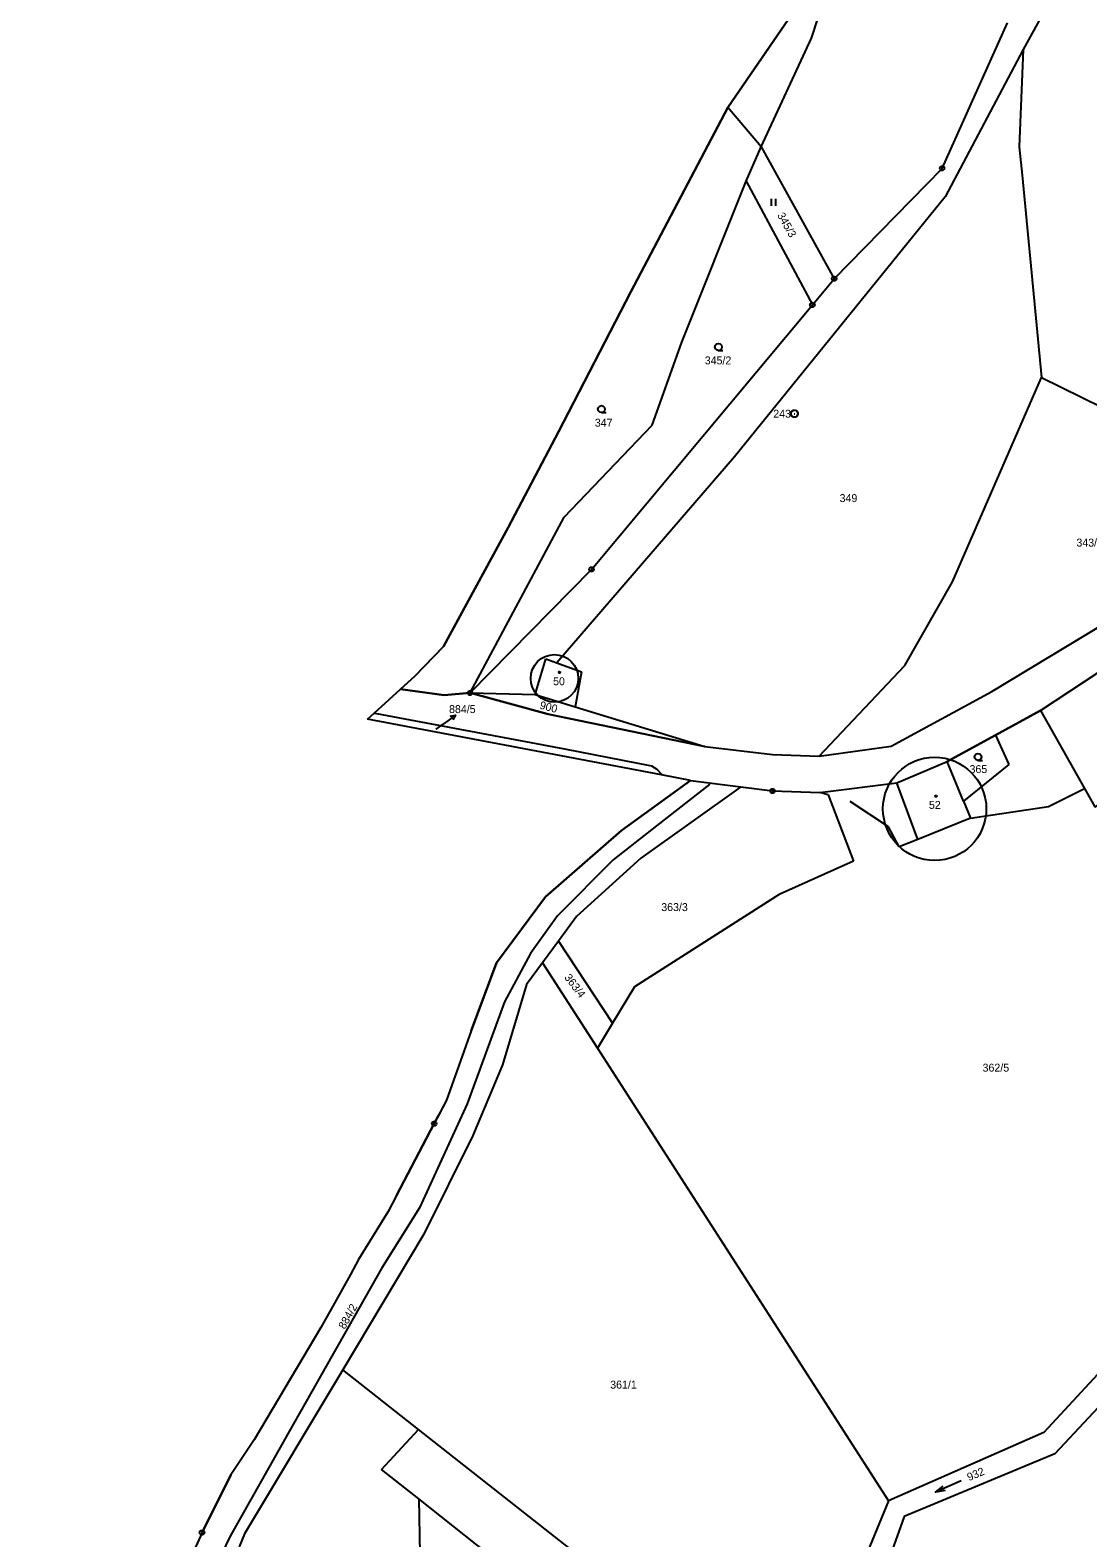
# Model space of a CAD drawing. Extents: x -580551 to -575069, y -1073031 to -1067931.
# Drawn here: x -577570.7 to -577343.9, y -1070091.5 to -1069768.1 of the extents above; entities that cross this region are included whole.
import ezdxf

# ---------------------------------------------------------------- set-up
doc = ezdxf.new("R2010")
doc.units = 0
for name, color, linetype in [('Druh pozemku', 7, 'Continuous'), ('Geodetické body', 7, 'Continuous'), ('Katastrální hranice', 7, 'Continuous'), ('Parcela', 7, 'Continuous'), ('Parcelní číslo', 7, 'Continuous'), ('Parcelní číslo_stavba', 7, 'Continuous'), ('Pomocná vrstva', 7, 'Continuous'), ('SR - hranice státu', 7, 'Continuous'), ('stavební parcely', 7, 'Continuous'), ('Vnitřní kresba', 7, 'Continuous'), ('Vrstva 6', 7, 'Continuous'), ('ČR - rámy ML', 7, 'Continuous')]:
    doc.layers.add(name, color=color, linetype=linetype)

msp = doc.modelspace()

# ---------------------------------------------------------------- linework, layer by layer
at = {"layer": 'Druh pozemku'}
for p, q in [((-577411.75, -1069804.33), (-577411.75, -1069805.83)), ((-577410.75, -1069805.83), (-577410.75, -1069804.33)), ((-577371.014, -1070079.312), (-577376.506, -1070081.728))]:
    msp.add_line(p, q, dxfattribs=at)
for points in [[(-577423.08, -1069836.83), (-577423.46, -1069836.73), (-577423.73, -1069836.46), (-577423.83, -1069836.09), (-577423.73, -1069835.72), (-577423.46, -1069835.45), (-577423.09, -1069835.35), (-577422.72, -1069835.45), (-577422.45, -1069835.72), (-577422.35, -1069836.1), (-577422.45, -1069836.48), (-577422.72, -1069836.75), (-577423.1, -1069836.85), (-577422.1, -1069836.85)], [(-577448.16, -1069850.15), (-577448.54, -1069850.05), (-577448.81, -1069849.78), (-577448.91, -1069849.41), (-577448.81, -1069849.04), (-577448.54, -1069848.77), (-577448.17, -1069848.67), (-577447.8, -1069848.77), (-577447.53, -1069849.04), (-577447.43, -1069849.42), (-577447.53, -1069849.8), (-577447.8, -1069850.07), (-577448.18, -1069850.17), (-577447.18, -1069850.17)], [(-577367.41, -1069924.76), (-577367.79, -1069924.66), (-577368.06, -1069924.39), (-577368.16, -1069924.02), (-577368.06, -1069923.65), (-577367.79, -1069923.38), (-577367.42, -1069923.28), (-577367.05, -1069923.38), (-577366.78, -1069923.65), (-577366.68, -1069924.03), (-577366.78, -1069924.41), (-577367.05, -1069924.68), (-577367.43, -1069924.78), (-577366.43, -1069924.78)], [(-577374.474, -1070081.38), (-577376.506, -1070081.728), (-577374.877, -1070080.465)]]:
    msp.add_lwpolyline(points, dxfattribs=at)
for points in [[(-577457.06, -1069905.73), (-577456.97, -1069905.88), (-577457.06, -1069906.03), (-577457.24, -1069906.03), (-577457.33, -1069905.88), (-577457.24, -1069905.73)], [(-577376.34, -1069932.27), (-577376.25, -1069932.42), (-577376.34, -1069932.57), (-577376.52, -1069932.57), (-577376.61, -1069932.42), (-577376.52, -1069932.27)]]:
    msp.add_lwpolyline(points, close=True, dxfattribs=at)
at = {"layer": 'Geodetické body'}
for p, q in [((-577375.24, -1069797.78), (-577375, -1069797.78)), ((-577398.38, -1069821.45), (-577398.14, -1069821.45)), ((-577403.06, -1069827.06), (-577402.82, -1069827.06)), ((-577406.82, -1069850.4), (-577406.72, -1069850.4)), ((-577450.41, -1069883.81), (-577450.17, -1069883.81)), ((-577476.45, -1069910.3), (-577476.21, -1069910.3)), ((-577411.59, -1069931.33), (-577411.35, -1069931.33)), ((-577484.14, -1070002.69), (-577483.9, -1070002.69)), ((-577533.93, -1070090.41), (-577533.69, -1070090.41))]:
    msp.add_line(p, q, dxfattribs=at)
for points in [[(-577374.97, -1069797.3), (-577374.72, -1069797.48), (-577374.62, -1069797.77), (-577374.72, -1069798.06), (-577374.97, -1069798.24), (-577375.28, -1069798.24), (-577375.53, -1069798.06), (-577375.63, -1069797.77), (-577375.53, -1069797.48), (-577375.28, -1069797.3)], [(-577398.11, -1069820.97), (-577397.86, -1069821.15), (-577397.76, -1069821.44), (-577397.86, -1069821.73), (-577398.11, -1069821.91), (-577398.42, -1069821.91), (-577398.67, -1069821.73), (-577398.77, -1069821.44), (-577398.67, -1069821.15), (-577398.42, -1069820.97)], [(-577402.79, -1069826.58), (-577402.54, -1069826.76), (-577402.44, -1069827.05), (-577402.54, -1069827.34), (-577402.79, -1069827.52), (-577403.1, -1069827.52), (-577403.35, -1069827.34), (-577403.45, -1069827.05), (-577403.35, -1069826.76), (-577403.1, -1069826.58)], [(-577406.58, -1069849.68), (-577406.24, -1069849.87), (-577406.05, -1069850.21), (-577406.05, -1069850.6), (-577406.24, -1069850.94), (-577406.58, -1069851.13), (-577406.97, -1069851.13), (-577407.31, -1069850.94), (-577407.5, -1069850.6), (-577407.5, -1069850.21), (-577407.31, -1069849.87), (-577406.97, -1069849.68)], [(-577450.14, -1069883.33), (-577449.89, -1069883.51), (-577449.79, -1069883.8), (-577449.89, -1069884.09), (-577450.14, -1069884.27), (-577450.45, -1069884.27), (-577450.7, -1069884.09), (-577450.8, -1069883.8), (-577450.7, -1069883.51), (-577450.45, -1069883.33)], [(-577476.18, -1069909.82), (-577475.93, -1069910), (-577475.83, -1069910.29), (-577475.93, -1069910.58), (-577476.18, -1069910.76), (-577476.49, -1069910.76), (-577476.74, -1069910.58), (-577476.84, -1069910.29), (-577476.74, -1069910), (-577476.49, -1069909.82)], [(-577411.32, -1069930.85), (-577411.07, -1069931.03), (-577410.97, -1069931.32), (-577411.07, -1069931.61), (-577411.32, -1069931.79), (-577411.63, -1069931.79), (-577411.88, -1069931.61), (-577411.98, -1069931.32), (-577411.88, -1069931.03), (-577411.63, -1069930.85)], [(-577483.87, -1070002.21), (-577483.62, -1070002.39), (-577483.52, -1070002.68), (-577483.62, -1070002.97), (-577483.87, -1070003.15), (-577484.18, -1070003.15), (-577484.43, -1070002.97), (-577484.53, -1070002.68), (-577484.43, -1070002.39), (-577484.18, -1070002.21)], [(-577533.66, -1070089.93), (-577533.41, -1070090.11), (-577533.31, -1070090.4), (-577533.41, -1070090.69), (-577533.66, -1070090.87), (-577533.97, -1070090.87), (-577534.22, -1070090.69), (-577534.32, -1070090.4), (-577534.22, -1070090.11), (-577533.97, -1070089.93)]]:
    msp.add_lwpolyline(points, close=True, dxfattribs=at)
at = {"layer": 'Katastrální hranice'}
for p, q in [((-577421.07, -1069784.74), (-577408.08, -1069765.76)), ((-577441.89, -1069824.3), (-577421.07, -1069784.74)), ((-577457.34, -1069854.3), (-577441.89, -1069824.3)), ((-577468.17, -1069874.85), (-577457.34, -1069854.3)), ((-577482, -1069900.31), (-577468.17, -1069874.85)), ((-577488.19, -1069906.73), (-577482, -1069900.31)), ((-577491.26, -1069909.51), (-577488.19, -1069906.73)), ((-577496.93, -1069914.65), (-577491.26, -1069909.51)), ((-577498.36, -1069915.94), (-577496.93, -1069914.65)), ((-577435.32, -1069927.87), (-577498.36, -1069915.94)), ((-577443.86, -1069939.81), (-577429.05, -1069929.06)), ((-577429.05, -1069929.06), (-577435.32, -1069927.87)), ((-577460.15, -1069954.05), (-577443.86, -1069939.81)), ((-577470.65, -1069968.18), (-577460.15, -1069954.05)), ((-577476.13, -1069982.8), (-577470.65, -1069968.18)), ((-577476.13, -1069982.8), (-577481.37, -1069997.64)), ((-577481.37, -1069997.64), (-577483.09, -1070000.91)), ((-577484.02, -1070002.69), (-577483.09, -1070000.91)), ((-577492.09, -1070018.1), (-577484.02, -1070002.69)), ((-577492.09, -1070018.1), (-577493.9, -1070021.54)), ((-577493.9, -1070021.54), (-577500.24, -1070031.8)), ((-577500.24, -1070031.8), (-577502.01, -1070035.04)), ((-577502.01, -1070035.04), (-577505.38, -1070041.2)), ((-577505.38, -1070041.2), (-577508.36, -1070046.45)), ((-577508.36, -1070046.45), (-577516.05, -1070059.43)), ((-577516.05, -1070059.43), (-577522.62, -1070070.51)), ((-577522.62, -1070070.51), (-577527.65, -1070078.04)), ((-577533.81, -1070090.41), (-577527.65, -1070078.04)), ((-577533.81, -1070090.41), (-577538.93, -1070101.78))]:
    msp.add_line(p, q, dxfattribs=at)
at = {"layer": 'Parcela'}
for p, q in [((-577403.1, -1069769.84), (-577393.88, -1069741.46)), ((-577352.75, -1069763.2), (-577357.71, -1069772.28)), ((-577375.12, -1069797.78), (-577361.12, -1069766.57)), ((-577413.89, -1069793.18), (-577403.1, -1069769.84)), ((-577357.71, -1069772.28), (-577374.49, -1069803.88)), ((-577357.71, -1069772.28), (-577358.61, -1069793.17)), ((-577413.89, -1069793.18), (-577421.07, -1069784.74)), ((-577417.11, -1069800.56), (-577413.89, -1069793.18)), ((-577358.61, -1069793.17), (-577357.92, -1069799.27)), ((-577430.91, -1069835.03), (-577417.11, -1069800.56)), ((-577417.11, -1069800.56), (-577402.94, -1069827.06)), ((-577398.26, -1069821.45), (-577375.12, -1069797.78)), ((-577357.92, -1069799.27), (-577353.77, -1069842.63)), ((-577374.49, -1069803.88), (-577419.64, -1069859.69)), ((-577402.94, -1069827.06), (-577398.26, -1069821.45)), ((-577450.29, -1069883.81), (-577402.94, -1069827.06)), ((-577437.26, -1069852.83), (-577430.91, -1069835.03)), ((-577372.89, -1069886.44), (-577353.77, -1069842.63)), ((-577353.77, -1069842.63), (-577295.46, -1069871.36)), ((-577456.16, -1069872.61), (-577437.26, -1069852.83)), ((-577419.64, -1069859.69), (-577457.76, -1069903.85)), ((-577476.33, -1069910.3), (-577456.16, -1069872.61)), ((-577476.33, -1069910.3), (-577450.29, -1069883.81)), ((-577383.08, -1069904.45), (-577372.89, -1069886.44)), ((-577364.42, -1069909.96), (-577323.38, -1069885.15)), ((-577462.35, -1069910.67), (-577460.09, -1069903.02)), ((-577460.09, -1069903.02), (-577457.76, -1069903.85)), ((-577457.76, -1069903.85), (-577452.41, -1069905.74)), ((-577354.01, -1069914.08), (-577338.5, -1069903.82)), ((-577452.41, -1069905.74), (-577453.79, -1069913.28)), ((-577401.5, -1069923.86), (-577383.08, -1069904.45)), ((-577481.87, -1069910.79), (-577491.26, -1069909.51)), ((-577476.33, -1069910.3), (-577481.87, -1069910.79)), ((-577476.33, -1069910.3), (-577462.35, -1069910.67)), ((-577459.62, -1069914.84), (-577476.33, -1069910.3)), ((-577462.35, -1069910.67), (-577453.79, -1069913.28)), ((-577386.06, -1069921.75), (-577364.42, -1069909.96)), ((-577453.79, -1069913.28), (-577425.96, -1069921.76)), ((-577496.93, -1069914.65), (-577496.39, -1069914.73)), ((-577496.39, -1069914.73), (-577456.11, -1069922.32)), ((-577425.96, -1069921.76), (-577459.62, -1069914.84)), ((-577354.01, -1069914.08), (-577363.65, -1069919.34)), ((-577354.01, -1069914.08), (-577344.57, -1069930.83)), ((-577363.65, -1069919.34), (-577374.01, -1069925)), ((-577363.65, -1069919.34), (-577360.78, -1069925.62)), ((-577456.11, -1069922.32), (-577437.45, -1069925.95)), ((-577425.96, -1069921.76), (-577411.47, -1069923.53)), ((-577411.47, -1069923.53), (-577401.5, -1069923.86)), ((-577401.5, -1069923.86), (-577386.06, -1069921.75)), ((-577437.45, -1069925.95), (-577436.26, -1069926.62)), ((-577436.26, -1069926.62), (-577435.39, -1069927.68)), ((-577384.83, -1069929.58), (-577374.01, -1069925)), ((-577370.54, -1069933.49), (-577374.01, -1069925)), ((-577360.78, -1069925.62), (-577370.54, -1069933.49)), ((-577435.39, -1069927.68), (-577435.32, -1069927.87)), ((-577429.05, -1069929.06), (-577418.27, -1069930.45)), ((-577401.32, -1069931.64), (-577384.83, -1069929.58)), ((-577418.27, -1069930.45), (-577439.75, -1069945.71)), ((-577418.27, -1069930.45), (-577411.47, -1069931.33)), ((-577411.47, -1069931.33), (-577401.32, -1069931.64)), ((-577399.54, -1069932.18), (-577401.32, -1069931.64)), ((-577399.54, -1069932.18), (-577394.13, -1069946.4)), ((-577352.3, -1069934.67), (-577344.57, -1069930.83)), ((-577344.57, -1069930.83), (-577342.36, -1069934.74)), ((-577386.63, -1069939.05), (-577394.82, -1069933.61)), ((-577369.02, -1069937.19), (-577352.3, -1069934.67)), ((-577384.31, -1069943.31), (-577386.63, -1069939.05)), ((-577369.02, -1069937.19), (-577380.32, -1069941.75)), ((-577380.32, -1069941.75), (-577384.31, -1069943.31)), ((-577439.75, -1069945.71), (-577453.49, -1069958.23)), ((-577394.13, -1069946.4), (-577410.03, -1069953.57)), ((-577410.03, -1069953.57), (-577441.1, -1069973.36)), ((-577453.49, -1069958.23), (-577457.38, -1069963.52)), ((-577457.38, -1069963.52), (-577460.81, -1069968.17)), ((-577460.81, -1069968.17), (-577464.24, -1069972.83)), ((-577460.81, -1069968.17), (-577449.04, -1069986.48)), ((-577464.24, -1069972.83), (-577469.35, -1069990.06)), ((-577441.1, -1069973.36), (-577445.79, -1069981.12)), ((-577445.79, -1069981.12), (-577449.04, -1069986.48)), ((-577449.04, -1069986.48), (-577386.61, -1070083.56)), ((-577469.35, -1069990.06), (-577475.74, -1070005.25)), ((-577475.74, -1070005.25), (-577486.23, -1070026.4)), ((-577486.23, -1070026.4), (-577503.65, -1070055.53)), ((-577331.64, -1070045.5), (-577353.32, -1070068.95)), ((-577331.77, -1070052.91), (-577350.91, -1070073.5)), ((-577503.65, -1070055.53), (-577524.68, -1070090.71)), ((-577487.4, -1070068.3), (-577503.65, -1070055.53)), ((-577495.3, -1070076.87), (-577487.4, -1070068.3)), ((-577425.08, -1070117.28), (-577487.4, -1070068.3)), ((-577353.32, -1070068.95), (-577386.61, -1070083.56)), ((-577350.91, -1070073.5), (-577383.27, -1070086.96)), ((-577487.34, -1070083.18), (-577495.3, -1070076.87)), ((-577487.34, -1070083.18), (-577486.78, -1070114.29)), ((-577435.61, -1070124.15), (-577487.34, -1070083.18)), ((-577386.61, -1070083.56), (-577391.64, -1070095.76)), ((-577383.27, -1070086.96), (-577387.33, -1070098.38)), ((-577524.68, -1070090.71), (-577525.83, -1070093.49))]:
    msp.add_line(p, q, dxfattribs=at)
at = {"layer": 'Parcelní číslo'}
msp.add_lwpolyline([(-577424.957, -1069929.888), (-577436.357, -1069938.804), (-577445.685, -1069946.1), (-577457.584, -1069958.078), (-577463.35, -1069966.207), (-577468.984, -1069976.565), (-577476.977, -1069998.462), (-577487.198, -1070020.752), (-577495.322, -1070033.732), (-577515.108, -1070068.74), (-577527.789, -1070091.178), (-577536.86, -1070110.042), (-577545.93, -1070128.906), (-577555.204, -1070143.477), (-577570.666, -1070151.737)], dxfattribs=at)
at = {"layer": 'Pomocná vrstva'}
for p in [(-577483.62, -1069918.09), (-577479.489, -1069915.069)]:
    msp.add_line(p, (-577481.91, -1069916.84), dxfattribs=at)
msp.add_lwpolyline([(-577480.591, -1069915.256), (-577479.489, -1069915.069), (-577480.001, -1069916.063)], dxfattribs=at)
at = {"layer": 'SR - hranice státu'}
for points in [[(-577386.06, -1069921.75), (-577364.42, -1069909.96), (-577323.38, -1069885.15), (-577295.46, -1069871.36), (-577290.48, -1069869.82), (-577285.62, -1069868.8)], [(-577491.26, -1069909.51), (-577481.87, -1069910.79), (-577476.33, -1069910.3), (-577459.62, -1069914.84), (-577425.96, -1069921.76), (-577411.47, -1069923.53), (-577401.5, -1069923.86), (-577386.06, -1069921.75)], [(-577401.32, -1069931.64), (-577384.83, -1069929.58), (-577374.01, -1069925), (-577363.65, -1069919.34), (-577354.01, -1069914.08)], [(-577354.01, -1069914.08), (-577344.57, -1069930.83), (-577342.36, -1069934.74), (-577329.51, -1069927.59)], [(-577429.05, -1069929.06), (-577418.27, -1069930.45), (-577411.47, -1069931.33), (-577401.32, -1069931.64)]]:
    msp.add_lwpolyline(points, dxfattribs=at)
at = {"layer": 'stavební parcely'}
for centre, radius in [((-577458.234, -1069907.177), 5.106), ((-577376.72, -1069935.17), 11.078)]:
    msp.add_circle(centre, radius, dxfattribs=at)
at = {"layer": 'Vnitřní kresba'}
for p, q in [((-577380.32, -1069941.75), (-577384.83, -1069929.58)), ((-577370.54, -1069933.49), (-577369.02, -1069937.19))]:
    msp.add_line(p, q, dxfattribs=at)
at = {"layer": 'Vrstva 6'}
for p, q in [((-577413.89, -1069793.18), (-577398.26, -1069821.45)), ((-577457.38, -1069963.52), (-577445.79, -1069981.12))]:
    msp.add_line(p, q, dxfattribs=at)
at = {"layer": 'ČR - rámy ML'}
for points in [[(-577405.32, -1069720.53), (-577405.91, -1069736.27), (-577408.08, -1069765.76), (-577421.07, -1069784.74), (-577441.89, -1069824.3), (-577457.34, -1069854.3), (-577468.17, -1069874.85), (-577482, -1069900.31), (-577488.19, -1069906.73), (-577491.26, -1069909.51)], [(-577429.05, -1069929.06), (-577443.86, -1069939.81), (-577460.15, -1069954.05), (-577470.65, -1069968.18), (-577476.13, -1069982.8), (-577481.37, -1069997.64), (-577484.02, -1070002.69), (-577492.09, -1070018.1), (-577493.9, -1070021.54), (-577500.24, -1070031.8), (-577502.01, -1070035.04), (-577505.38, -1070041.2), (-577508.36, -1070046.45), (-577516.05, -1070059.43), (-577522.62, -1070070.51), (-577527.65, -1070078.04), (-577533.81, -1070090.41), (-577538.93, -1070101.78)]]:
    msp.add_lwpolyline(points, dxfattribs=at)

# ---------------------------------------------------------------- texts
at = {"layer": 'Geodetické body'}
msp.add_text('243', height=1.7, dxfattribs=at).set_placement((-577411.319, -1069851.25))
at = {"layer": 'Parcelní číslo'}
for s, rotation, p in [('345/3', 299.08397, (-577410.527, -1069807.822)), ('900', 345.55085, (-577461.525, -1069913.658)), ('363/4', 307.16267, (-577456.223, -1069971.364)), ('884/2', 61.02001, (-577503.192, -1070046.918)), ('932', 23.0329, (-577369.337, -1070079.39))]:
    msp.add_text(s, height=1.7, rotation=rotation, dxfattribs=at).set_placement(p)
for s, height, p in [('345/2', 1.7, (-577426.012, -1069839.83)), ('347', 1.7, (-577449.586, -1069853.18)), ('349', 1.7, (-577397.091, -1069869.36)), ('343/1', 1.7, (-577346.316, -1069878.91)), ('884/5', 0.1, (-577483.828, -1069918.09)), ('365', 1.7, (-577369.232, -1069927.49)), ('363/3', 1.7, (-577435.34, -1069957.09)), ('362/5', 1.7, (-577366.432, -1069991.53)), ('361/1', 1.7, (-577446.282, -1070059.52))]:
    msp.add_text(s, height=height, dxfattribs=at).set_placement(p)
at = {"layer": 'Parcelní číslo_stavba'}
for s, p in [('50', (-577458.531, -1069908.65)), ('52', (-577377.942, -1069935.17))]:
    msp.add_text(s, height=1.7, dxfattribs=at).set_placement(p)
at = {"layer": 'Pomocná vrstva'}
msp.add_text('884/5', height=1.7, dxfattribs=at).set_placement((-577480.838, -1069914.62))

doc.saveas('drawing.dxf')
